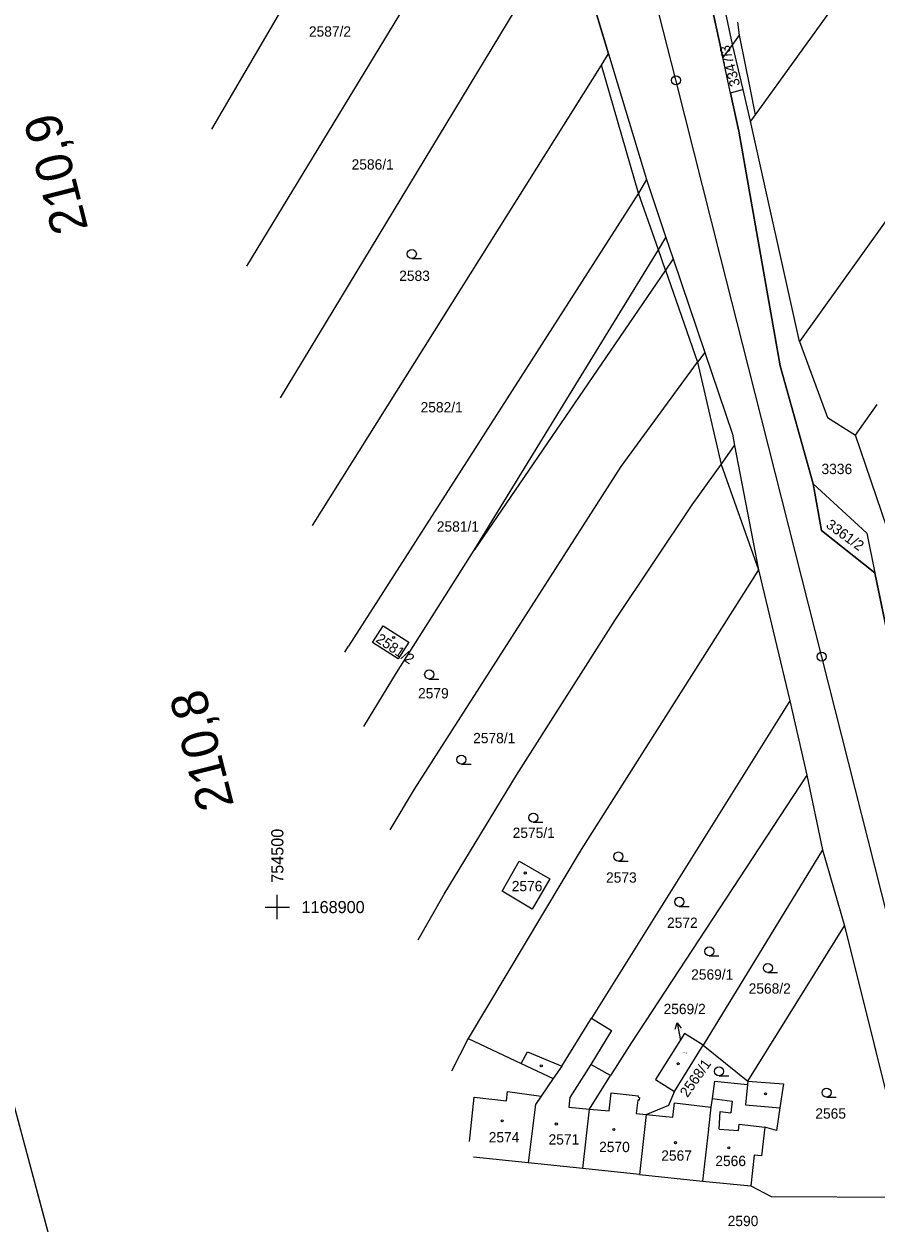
# Model space of a CAD drawing. Extents: x -754710 to -754206, y -1169123 to -1168234.
# Drawn here: x -754541.8 to -754401.2, y -1168952.2 to -1168754.2 of the extents above; entities that cross this region are included whole.
import ezdxf

# ---------------------------------------------------------------- set-up
doc = ezdxf.new("R2010")
doc.units = 0
for name, color, linetype in [('Implicitní', 7, 'Continuous'), ('Vrstva 1', 7, 'Continuous'), ('Vrstva 16', 7, 'Continuous'), ('Vrstva 18', 7, 'Continuous'), ('Vrstva 19', 7, 'Continuous'), ('Vrstva 25', 7, 'Continuous'), ('Vrstva 3', 7, 'Continuous'), ('Vrstva 4', 7, 'Continuous'), ('Vrstva 6', 7, 'Continuous'), ('Vrstva 61', 7, 'Continuous'), ('Vrstva 7', 7, 'Continuous')]:
    doc.layers.add(name, color=color, linetype=linetype)

msp = doc.modelspace()

# ---------------------------------------------------------------- linework, layer by layer
at = {"layer": 'Implicitní'}
for points in [[(-754500, -1168902), (-754500, -1168900), (-754500, -1168898)], [(-754502, -1168900), (-754500, -1168900), (-754498, -1168900)]]:
    msp.add_lwpolyline(points, dxfattribs=at)
at = {"layer": 'Vrstva 1'}
for p, q in [((-754510.83, -1168771.56), (-754468.68, -1168699.59)), ((-754457.95, -1168716.5), (-754505.08, -1168794.17)), ((-754394.02, -1168731.56), (-754421.18, -1168769.2)), ((-754451.95, -1168737.18), (-754499.53, -1168815.95)), ((-754445.36, -1168759.13), (-754451.95, -1168737.18)), ((-754431.15, -1168738.1), (-754426.48, -1168759.73)), ((-754434.25, -1168763.41), (-754439.13, -1168744.08)), ((-754424.07, -1168753.9), (-754423.79, -1168756.05)), ((-754423.79, -1168756.05), (-754424.91, -1168757.57)), ((-754423.79, -1168756.05), (-754422.04, -1168764.73)), ((-754446.52, -1168760.99), (-754445.36, -1168759.13)), ((-754445.36, -1168759.13), (-754439.11, -1168779.87)), ((-754425.2, -1168765.6), (-754426.48, -1168759.73)), ((-754494.17, -1168837.03), (-754446.52, -1168760.99)), ((-754426.85, -1168792.67), (-754434.25, -1168763.41)), ((-754425.2, -1168765.6), (-754423.83, -1168771.88)), ((-754421.93, -1168770.23), (-754423.15, -1168765.02)), ((-754422.04, -1168764.73), (-754421.18, -1168769.2)), ((-754421.18, -1168769.2), (-754421.93, -1168770.23)), ((-754413.83, -1168806.63), (-754421.93, -1168770.23)), ((-754423.83, -1168771.88), (-754417.05, -1168810.66)), ((-754389.49, -1168772.51), (-754413.83, -1168806.63)), ((-754439.11, -1168779.87), (-754440.39, -1168782.12)), ((-754439.11, -1168779.87), (-754435.88, -1168789.44)), ((-754440.39, -1168782.12), (-754488.24, -1168856.95)), ((-754435.88, -1168789.44), (-754434.68, -1168792.97)), ((-754434.68, -1168792.97), (-754429.46, -1168808.42)), ((-754422.26, -1168810.85), (-754426.85, -1168792.67)), ((-754413.83, -1168806.63), (-754409.23, -1168819.18)), ((-754443.28, -1168827.28), (-754430.65, -1168810.04)), ((-754429.46, -1168808.42), (-754430.65, -1168810.04)), ((-754429.46, -1168808.42), (-754424.9, -1168821.92)), ((-754410.17, -1168858.68), (-754422.26, -1168810.85)), ((-754417.05, -1168810.66), (-754411.61, -1168830.11)), ((-754404.58, -1168822.1), (-754401.03, -1168817.01)), ((-754409.23, -1168819.18), (-754404.58, -1168822.1)), ((-754424.9, -1168821.92), (-754424.54, -1168823.8)), ((-754426.79, -1168826.94), (-754424.54, -1168823.8)), ((-754424.54, -1168823.8), (-754420.6, -1168844.33)), ((-754396.3, -1168846.57), (-754404.58, -1168822.1)), ((-754477.37, -1168880.54), (-754443.28, -1168827.28)), ((-754431.55, -1168833.59), (-754426.79, -1168826.94)), ((-754411.61, -1168830.11), (-754402.76, -1168838.28)), ((-754444.22, -1168852.55), (-754431.55, -1168833.59)), ((-754402.76, -1168838.28), (-754401.41, -1168844.82)), ((-754480.34, -1168861.35), (-754467.51, -1168841.1)), ((-754420.6, -1168844.33), (-754449.89, -1168890.49)), ((-754420.6, -1168844.33), (-754415.45, -1168865.96)), ((-754401.41, -1168844.82), (-754396.56, -1168868.29)), ((-754484.32, -1168856.31), (-754482.56, -1168853.56)), ((-754482.56, -1168853.56), (-754478.3, -1168856.26)), ((-754460.56, -1168878.23), (-754444.22, -1168852.55)), ((-754488.84, -1168857.94), (-754488.24, -1168856.95)), ((-754480.05, -1168859.02), (-754484.32, -1168856.31)), ((-754478.3, -1168856.26), (-754480.05, -1168859.02)), ((-754485.72, -1168870.19), (-754480.34, -1168861.35)), ((-754415.45, -1168865.96), (-754448.17, -1168918.32)), ((-754415.45, -1168865.96), (-754412.65, -1168878.24)), ((-754472.47, -1168897.88), (-754460.56, -1168878.23)), ((-754412.65, -1168878.24), (-754441.58, -1168922.39)), ((-754412.65, -1168878.24), (-754410.06, -1168890.53)), ((-754481.38, -1168887.25), (-754477.37, -1168880.54)), ((-754449.89, -1168890.49), (-754468.49, -1168921.69)), ((-754410.06, -1168890.53), (-754429.73, -1168922.78)), ((-754410.06, -1168890.53), (-754406.43, -1168903.09)), ((-754462.92, -1168897.4), (-754460.07, -1168892.45)), ((-754460.07, -1168892.45), (-754455.03, -1168895.36)), ((-754455.03, -1168895.36), (-754457.95, -1168900.33)), ((-754476.76, -1168905.42), (-754472.47, -1168897.88)), ((-754457.95, -1168900.33), (-754462.92, -1168897.4)), ((-754422.39, -1168928.77), (-754406.43, -1168903.09)), ((-754406.43, -1168903.09), (-754396.05, -1168944.82)), ((-754453.08, -1168926.28), (-754448.17, -1168918.32)), ((-754448.17, -1168918.32), (-754444.86, -1168920.39)), ((-754444.86, -1168920.39), (-754448.28, -1168926)), ((-754432.81, -1168920.9), (-754437.59, -1168928.48)), ((-754429.73, -1168922.78), (-754432.81, -1168920.9)), ((-754468.49, -1168921.69), (-754471.24, -1168927.11)), ((-754468.49, -1168921.69), (-754459.74, -1168925.82)), ((-754441.58, -1168922.39), (-754445.02, -1168927.83)), ((-754434.48, -1168930.44), (-754429.73, -1168922.78)), ((-754429.73, -1168922.78), (-754422.39, -1168928.77)), ((-754459.74, -1168925.82), (-754458.72, -1168923.88)), ((-754458.72, -1168923.88), (-754453.08, -1168926.28)), ((-754453.08, -1168926.28), (-754454.46, -1168928.29)), ((-754445.02, -1168927.83), (-754448.28, -1168926)), ((-754454.46, -1168928.29), (-754456.49, -1168931.25)), ((-754448.49, -1168933.38), (-754445.02, -1168927.83)), ((-754437.59, -1168928.48), (-754434.48, -1168930.44)), ((-754427.85, -1168928.75), (-754428.24, -1168931.61)), ((-754427.85, -1168928.75), (-754422.44, -1168929.31)), ((-754422.39, -1168928.77), (-754422.44, -1168929.31)), ((-754422.39, -1168928.77), (-754416.46, -1168929.19)), ((-754445.25, -1168933.67), (-754444.92, -1168930.69)), ((-754444.92, -1168930.69), (-754440.44, -1168931.16)), ((-754435.41, -1168932.72), (-754434.48, -1168930.44)), ((-754416.46, -1168929.19), (-754417.07, -1168933.14)), ((-754457.42, -1168932.6), (-754458.62, -1168942.21)), ((-754456.49, -1168931.25), (-754457.42, -1168932.6)), ((-754440.52, -1168931.87), (-754440.77, -1168934.08)), ((-754440.31, -1168931.89), (-754440.52, -1168931.87)), ((-754440.44, -1168931.16), (-754440.47, -1168931.4)), ((-754440.47, -1168931.4), (-754440.26, -1168931.42)), ((-754440.26, -1168931.42), (-754440.31, -1168931.89)), ((-754439.14, -1168934.23), (-754435.41, -1168932.72)), ((-754434.76, -1168934.72), (-754434.48, -1168932.33)), ((-754434.48, -1168932.33), (-754428.45, -1168933.04)), ((-754428.24, -1168931.61), (-754428.45, -1168933.04)), ((-754449.57, -1168943.16), (-754448.49, -1168933.38)), ((-754448.49, -1168933.38), (-754445.25, -1168933.67)), ((-754440.77, -1168934.08), (-754439.14, -1168934.23)), ((-754439.14, -1168934.23), (-754440.24, -1168944.14)), ((-754439.14, -1168934.23), (-754435.9, -1168934.59)), ((-754435.9, -1168934.59), (-754434.76, -1168934.72)), ((-754428.45, -1168933.04), (-754428.84, -1168936.55)), ((-754417.07, -1168933.14), (-754417.65, -1168936.92)), ((-754428.86, -1168936.68), (-754429.85, -1168945.24)), ((-754428.86, -1168936.68), (-754428.84, -1168936.55)), ((-754419.59, -1168936.35), (-754420.13, -1168941.08)), ((-754417.65, -1168936.92), (-754419.59, -1168936.35)), ((-754458.62, -1168942.21), (-754467.63, -1168941.27)), ((-754449.57, -1168943.16), (-754458.62, -1168942.21)), ((-754421.31, -1168940.95), (-754421.89, -1168946.03)), ((-754420.13, -1168941.08), (-754421.31, -1168940.95)), ((-754440.24, -1168944.14), (-754449.57, -1168943.16)), ((-754440.24, -1168944.14), (-754429.85, -1168945.24)), ((-754429.85, -1168945.24), (-754421.89, -1168946.03)), ((-754421.89, -1168946.03), (-754418.54, -1168947.81)), ((-754418.54, -1168947.81), (-754396.5, -1168947.91))]:
    msp.add_line(p, q, dxfattribs=at)
for points in [[(-754378.16, -1168960.13), (-754379.05, -1168945.33), (-754396.56, -1168868.29), (-754401.41, -1168844.82), (-754410.22, -1168837.85), (-754411.61, -1168830.11), (-754417.05, -1168810.66), (-754423.83, -1168771.88), (-754425.2, -1168765.6), (-754426.48, -1168759.73), (-754431.15, -1168738.1), (-754436.63, -1168712.73), (-754441.87, -1168691.36), (-754448.68, -1168663.63), (-754450.74, -1168651.41), (-754451.5, -1168646.92), (-754451.93, -1168644.34), (-754452.67, -1168639.96), (-754460.6, -1168619.67)], [(-754451.95, -1168737.18), (-754445.36, -1168759.13), (-754439.11, -1168779.87), (-754435.88, -1168789.44), (-754434.68, -1168792.97), (-754429.46, -1168808.42), (-754424.9, -1168821.92), (-754424.54, -1168823.8), (-754420.6, -1168844.33), (-754415.45, -1168865.96), (-754412.65, -1168878.24), (-754410.06, -1168890.53), (-754406.43, -1168903.09), (-754396.05, -1168944.82), (-754394.57, -1168948.26), (-754386.06, -1168980.52)], [(-754367.04, -1169029.33), (-754371.5, -1169011.68), (-754383.94, -1168962.43), (-754384.99, -1168958.29), (-754386.56, -1168952.08), (-754387.62, -1168947.84), (-754397.03, -1168910.64), (-754410.17, -1168858.68)]]:
    msp.add_lwpolyline(points, dxfattribs=at)
for centre in [(-754434.23, -1168763.49), (-754410.17, -1168858.65)]:
    msp.add_circle(centre, 0.75, dxfattribs=at)
at = {"layer": 'Vrstva 16'}
msp.add_line((-754434, -1168919.1), (-754433.5, -1168922.06), dxfattribs=at)
msp.add_lwpolyline([(-754434.33, -1168920.17), (-754434, -1168919.1), (-754433.34, -1168920.01)], dxfattribs=at)
at = {"layer": 'Vrstva 25'}
for p, q in [((-754477.81, -1168792.92), (-754476.21, -1168792.92)), ((-754474.94, -1168862.35), (-754473.34, -1168862.35)), ((-754469.62, -1168876.41), (-754468.02, -1168876.41)), ((-754457.77, -1168886), (-754456.17, -1168886)), ((-754443.72, -1168892.41), (-754442.12, -1168892.41)), ((-754433.67, -1168899.89), (-754432.07, -1168899.89)), ((-754428.73, -1168908.07), (-754427.13, -1168908.07)), ((-754419.06, -1168910.83), (-754417.46, -1168910.83)), ((-754427.11, -1168927.88), (-754425.51, -1168927.88)), ((-754409.38, -1168931.38), (-754407.78, -1168931.38))]:
    msp.add_line(p, q, dxfattribs=at)
for centre, radius in [((-754477.81, -1168792.17), 0.75), ((-754480.81, -1168855.5), 0.175), ((-754474.94, -1168861.6), 0.75), ((-754469.62, -1168875.66), 0.75), ((-754457.77, -1168885.25), 0.75), ((-754443.72, -1168891.66), 0.75), ((-754459.09, -1168894.37), 0.175), ((-754433.67, -1168899.14), 0.75), ((-754428.73, -1168907.32), 0.75), ((-754419.06, -1168910.08), 0.75), ((-754456.44, -1168926.22), 0.175), ((-754433.86, -1168925.87), 0.175), ((-754427.11, -1168927.13), 0.75), ((-754419.44, -1168930.85), 0.175), ((-754409.38, -1168930.63), 0.75), ((-754462.89, -1168935.3), 0.175), ((-754453.97, -1168935.83), 0.175), ((-754444.48, -1168936.72), 0.175), ((-754434.3, -1168938.91), 0.175), ((-754425.51, -1168939.75), 0.175)]:
    msp.add_circle(centre, radius, dxfattribs=at)
at = {"layer": 'Vrstva 3'}
msp.add_lwpolyline([(-754710.01, -1168311.22), (-754492.6, -1169122.6), (-754205.72, -1169045.73), (-754423.13, -1168234.35)], close=True, dxfattribs=at)
at = {"layer": 'Vrstva 4'}
for p, q in [((-754424.91, -1168757.57), (-754429.57, -1168735.76)), ((-754423.15, -1168765.02), (-754424.91, -1168757.57)), ((-754440.39, -1168782.12), (-754446.52, -1168760.99)), ((-754437.13, -1168791.48), (-754440.39, -1168782.12)), ((-754435.96, -1168794.84), (-754437.13, -1168791.48)), ((-754434.68, -1168792.97), (-754435.96, -1168794.84)), ((-754435.96, -1168794.84), (-754467.51, -1168841.1)), ((-754435.96, -1168794.84), (-754430.65, -1168810.04)), ((-754430.65, -1168810.04), (-754426.79, -1168826.94)), ((-754426.79, -1168826.94), (-754420.6, -1168844.33)), ((-754459.74, -1168925.82), (-754454.46, -1168928.29)), ((-754448.28, -1168926), (-754451.73, -1168931.44)), ((-754462.19, -1168931.99), (-754462.02, -1168930.44)), ((-754462.02, -1168930.44), (-754456.49, -1168931.25)), ((-754422.44, -1168929.31), (-754422.75, -1168932.64)), ((-754468.28, -1168938.72), (-754467.54, -1168931.41)), ((-754467.54, -1168931.41), (-754462.19, -1168931.99)), ((-754451.73, -1168931.44), (-754451.89, -1168933.04)), ((-754428.24, -1168931.61), (-754424.95, -1168932.04)), ((-754424.95, -1168932.04), (-754425.19, -1168934)), ((-754422.75, -1168932.64), (-754417.07, -1168933.14)), ((-754451.89, -1168933.04), (-754448.49, -1168933.38)), ((-754427.12, -1168936.68), (-754426.91, -1168933.76)), ((-754426.91, -1168933.76), (-754425.19, -1168934)), ((-754427.12, -1168936.68), (-754423.92, -1168936.91)), ((-754423.92, -1168936.91), (-754423.8, -1168935.86)), ((-754423.8, -1168935.86), (-754419.59, -1168936.35))]:
    msp.add_line(p, q, dxfattribs=at)
at = {"layer": 'Vrstva 6'}
for p, q in [((-754424.91, -1168757.57), (-754426.48, -1168759.73)), ((-754423.15, -1168765.02), (-754425.2, -1168765.6)), ((-754437.13, -1168791.48), (-754435.88, -1168789.44)), ((-754467.51, -1168841.1), (-754437.13, -1168791.48)), ((-754411.61, -1168830.11), (-754410.22, -1168837.85)), ((-754410.22, -1168837.85), (-754401.41, -1168844.82))]:
    msp.add_line(p, q, dxfattribs=at)
at = {"layer": 'Vrstva 61'}
msp.add_line((-754710.01, -1168311.22), (-754492.6, -1169122.6), dxfattribs=at)

# ---------------------------------------------------------------- texts
at = {"layer": 'Implicitní'}
msp.add_text('754500', height=2, rotation=90, dxfattribs=at).set_placement((-754499, -1168896))
msp.add_text('1168900', height=2, dxfattribs=at).set_placement((-754496, -1168901))
at = {"layer": 'Vrstva 16'}
msp.add_text('2569/2', height=1.7, dxfattribs=at).set_placement((-754436.27, -1168917.68))
at = {"layer": 'Vrstva 18'}
for s, p in [('2587/2', (-754494.79, -1168756.29)), ('2586/1', (-754487.74, -1168778.24)), ('2583', (-754479.89, -1168796.62)), ('2582/1', (-754476.36, -1168818.33)), ('3336', (-754410.21, -1168828.52)), ('2581/1', (-754473.68, -1168838.02)), ('2579', (-754476.78, -1168865.55)), ('2578/1', (-754467.69, -1168872.95)), ('2575/1', (-754461.17, -1168888.59)), ('2573', (-754445.76, -1168895.97)), ('2572', (-754435.7, -1168903.44)), ('2569/1', (-754431.72, -1168911.99)), ('2568/2', (-754422.23, -1168914.3)), ('2565', (-754411.23, -1168934.94)), ('2590', (-754425.69, -1168952.68))]:
    msp.add_text(s, height=1.7, dxfattribs=at).set_placement(p)
for s, rotation, p in [('3347/3', 105.3669, (-754423.61, -1168764.27)), ('3361/2', 324.0076, (-754409.62, -1168837.2)), ('2568/1', 54.8894, (-754432.33, -1168931.55))]:
    msp.add_text(s, height=1.7, rotation=rotation, dxfattribs=at).set_placement(p)
at = {"layer": 'Vrstva 19'}
msp.add_text('2581/2', height=1.7, rotation=325.8984, dxfattribs=at).set_placement((-754483.89, -1168856.11))
for s, height, p in [('2576', 1.7, (-754461.32, -1168897.39)), ('2569/2', 0.2, (-754433.12, -1168924.18)), ('2574', 1.7, (-754465.12, -1168938.86)), ('2571', 1.7, (-754455.25, -1168939.22)), ('2570', 1.7, (-754446.9, -1168940.46)), ('2567', 1.7, (-754436.65, -1168941.88)), ('2566', 1.7, (-754427.73, -1168942.77))]:
    msp.add_text(s, height=height, dxfattribs=at).set_placement(p)
at = {"layer": 'Vrstva 7'}
for s, rotation, p in [('210,9', 104.1882, (-754531.18, -1168787.99)), ('210,8', 104.184, (-754507.12, -1168883.17))]:
    msp.add_text(s, height=6, rotation=rotation, dxfattribs=at).set_placement(p)

doc.saveas('drawing.dxf')
